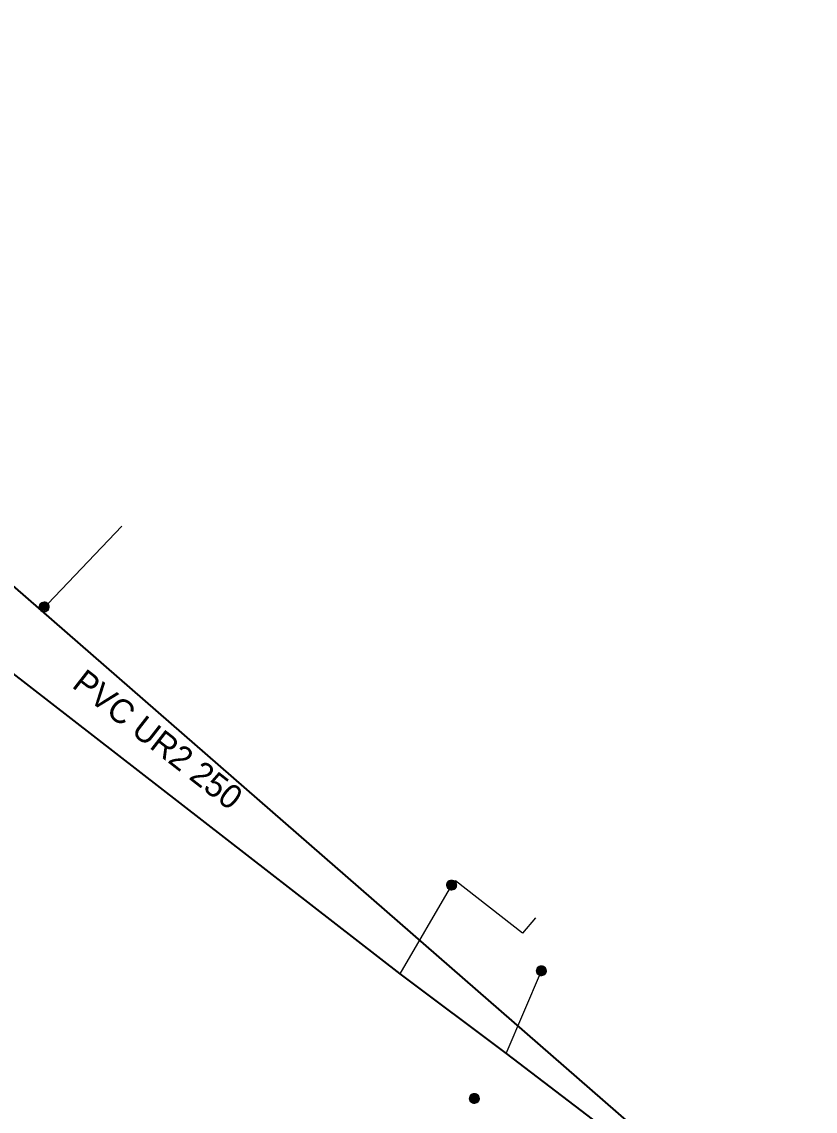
# Model space of a CAD drawing. Extents: x -873619 to -867639, y -1015082 to -1012326.
# Drawn here: x -868129.55 to -868093.3, y -1012775.89 to -1012726.16 of the extents above; entities that cross this region are included whole.
import ezdxf

# ---------------------------------------------------------------- set-up
doc = ezdxf.new("R2010")
doc.units = 0
doc.header["$LTSCALE"] = 0.44
for name, color, linetype, lineweight in [('1', 7, 'Continuous', 13), ('12', 7, 'Continuous', 13), ('21', 7, 'Continuous', 35), ('23', 7, 'Continuous', 25), ('3', 7, 'Continuous', 25), ('32', 7, 'Continuous', 13)]:
    doc.layers.add(name, color=color, linetype=linetype, lineweight=lineweight)

msp = doc.modelspace()

# ---------------------------------------------------------------- linework, layer by layer
at = {"layer": '1', "lineweight": 35}
msp.add_lwpolyline([(-868094.808, -1012782.506), (-868128.65, -1012753.034), (-868142.107, -1012741.315), (-868163.447, -1012723.713), (-868165.629, -1012721.604), (-868186.647, -1012703.368), (-868189.69, -1012700.802), (-868224.291, -1012669.746), (-868245.779, -1012651.034), (-868246.236, -1012651.387)], dxfattribs=at)
at = {"layer": '12'}
for points in [[(-868128.293, -1012752.869), (-868128.299, -1012752.817), (-868128.316, -1012752.767), (-868128.345, -1012752.723), (-868128.382, -1012752.686), (-868128.427, -1012752.659), (-868128.477, -1012752.642), (-868128.53, -1012752.638), (-868128.581, -1012752.645), (-868128.63, -1012752.664), (-868128.674, -1012752.693), (-868128.71, -1012752.732), (-868128.736, -1012752.777), (-868128.752, -1012752.828), (-868128.755, -1012752.88), (-868128.747, -1012752.932), (-868128.727, -1012752.981), (-868128.696, -1012753.024), (-868128.657, -1012753.058), (-868128.611, -1012753.084), (-868128.559, -1012753.098), (-868128.507, -1012753.1), (-868128.456, -1012753.09), (-868128.407, -1012753.069), (-868128.365, -1012753.038), (-868128.331, -1012752.997), (-868128.307, -1012752.951), (-868128.294, -1012752.9)], [(-868128.323, -1012752.869), (-868128.329, -1012752.82), (-868128.346, -1012752.774), (-868128.374, -1012752.734), (-868128.411, -1012752.702), (-868128.455, -1012752.68), (-868128.503, -1012752.669), (-868128.552, -1012752.669), (-868128.598, -1012752.682), (-868128.642, -1012752.706), (-868128.678, -1012752.739), (-868128.705, -1012752.78), (-868128.721, -1012752.827), (-868128.725, -1012752.876), (-868128.718, -1012752.924), (-868128.699, -1012752.969), (-868128.669, -1012753.009), (-868128.63, -1012753.04), (-868128.587, -1012753.06), (-868128.539, -1012753.07), (-868128.49, -1012753.068), (-868128.443, -1012753.053), (-868128.4, -1012753.028), (-868128.365, -1012752.994), (-868128.34, -1012752.952), (-868128.326, -1012752.905)], [(-868128.353, -1012752.869), (-868128.358, -1012752.824), (-868128.375, -1012752.782), (-868128.404, -1012752.747), (-868128.44, -1012752.72), (-868128.482, -1012752.703), (-868128.527, -1012752.698), (-868128.571, -1012752.704), (-868128.613, -1012752.723), (-868128.647, -1012752.751), (-868128.674, -1012752.788), (-868128.691, -1012752.83), (-868128.695, -1012752.875), (-868128.688, -1012752.92), (-868128.669, -1012752.961), (-868128.64, -1012752.995), (-868128.603, -1012753.021), (-868128.559, -1012753.037), (-868128.515, -1012753.04), (-868128.47, -1012753.032), (-868128.429, -1012753.012), (-868128.396, -1012752.983), (-868128.37, -1012752.945), (-868128.356, -1012752.902)], [(-868128.383, -1012752.869), (-868128.387, -1012752.828), (-868128.406, -1012752.791), (-868128.433, -1012752.76), (-868128.468, -1012752.739), (-868128.508, -1012752.728), (-868128.549, -1012752.73), (-868128.588, -1012752.743), (-868128.622, -1012752.767), (-868128.647, -1012752.799), (-868128.662, -1012752.837), (-868128.664, -1012752.878), (-868128.657, -1012752.918), (-868128.637, -1012752.954), (-868128.608, -1012752.983), (-868128.571, -1012753.002), (-868128.531, -1012753.01), (-868128.49, -1012753.006), (-868128.451, -1012752.991), (-868128.419, -1012752.965), (-868128.397, -1012752.931), (-868128.384, -1012752.892)], [(-868128.413, -1012752.869), (-868128.418, -1012752.833), (-868128.436, -1012752.801), (-868128.462, -1012752.776), (-868128.495, -1012752.761), (-868128.532, -1012752.758), (-868128.566, -1012752.766), (-868128.598, -1012752.786), (-868128.62, -1012752.814), (-868128.634, -1012752.848), (-868128.634, -1012752.885), (-868128.623, -1012752.92), (-868128.602, -1012752.949), (-868128.571, -1012752.97), (-868128.537, -1012752.98), (-868128.5, -1012752.978), (-868128.466, -1012752.964), (-868128.439, -1012752.941), (-868128.419, -1012752.909), (-868128.413, -1012752.874)], [(-868128.443, -1012752.869), (-868128.448, -1012752.838), (-868128.465, -1012752.812), (-868128.49, -1012752.795), (-868128.521, -1012752.788), (-868128.552, -1012752.792), (-868128.579, -1012752.809), (-868128.597, -1012752.833), (-868128.605, -1012752.864), (-868128.601, -1012752.894), (-868128.586, -1012752.922), (-868128.561, -1012752.941), (-868128.532, -1012752.95), (-868128.5, -1012752.947), (-868128.473, -1012752.933), (-868128.453, -1012752.909), (-868128.443, -1012752.88)], [(-868128.473, -1012752.869), (-868128.478, -1012752.845), (-868128.495, -1012752.827), (-868128.517, -1012752.818), (-868128.542, -1012752.821), (-868128.563, -1012752.835), (-868128.574, -1012752.857), (-868128.574, -1012752.882), (-868128.561, -1012752.903), (-868128.542, -1012752.917), (-868128.517, -1012752.92), (-868128.494, -1012752.911), (-868128.478, -1012752.893)], [(-868128.503, -1012752.869), (-868128.508, -1012752.854), (-868128.522, -1012752.848), (-868128.538, -1012752.852), (-868128.544, -1012752.866), (-868128.541, -1012752.881), (-868128.527, -1012752.89), (-868128.512, -1012752.887), (-868128.503, -1012752.875)]]:
    msp.add_lwpolyline(points, close=True, dxfattribs=at)
at = {"layer": '21'}
msp.add_lwpolyline([(-868134.19, -1012752.63), (-868112.27, -1012769.62), (-868107.42, -1012773.25), (-868101.75, -1012777.58), (-868093.15, -1012793.25), (-868087.37, -1012839.18), (-868062.459, -1012846.83), (-868020.28, -1012856.9)], dxfattribs=at)
at = {"layer": '23'}
msp.add_line((-868107.42, -1012773.25), (-868105.81, -1012769.48), dxfattribs=at)
msp.add_lwpolyline([(-868106.08, -1012767.07), (-868106.67, -1012767.76), (-868109.73, -1012765.38), (-868109.91, -1012765.57), (-868112.27, -1012769.62)], dxfattribs=at)
at = {"layer": '3'}
msp.add_line((-868128.666, -1012753.048), (-868124.972, -1012749.183), dxfattribs=at)
at = {"layer": '32'}
for points in [[(-868109.679, -1012765.569), (-868109.686, -1012765.517), (-868109.703, -1012765.467), (-868109.732, -1012765.423), (-868109.769, -1012765.386), (-868109.814, -1012765.359), (-868109.864, -1012765.342), (-868109.917, -1012765.338), (-868109.968, -1012765.345), (-868110.017, -1012765.364), (-868110.061, -1012765.393), (-868110.097, -1012765.432), (-868110.123, -1012765.477), (-868110.139, -1012765.528), (-868110.142, -1012765.58), (-868110.134, -1012765.632), (-868110.114, -1012765.681), (-868110.083, -1012765.724), (-868110.044, -1012765.758), (-868109.998, -1012765.784), (-868109.946, -1012765.798), (-868109.894, -1012765.8), (-868109.843, -1012765.79), (-868109.794, -1012765.769), (-868109.752, -1012765.738), (-868109.718, -1012765.697), (-868109.694, -1012765.651), (-868109.681, -1012765.6)], [(-868109.71, -1012765.569), (-868109.716, -1012765.52), (-868109.733, -1012765.474), (-868109.761, -1012765.434), (-868109.798, -1012765.402), (-868109.842, -1012765.38), (-868109.89, -1012765.369), (-868109.939, -1012765.369), (-868109.985, -1012765.382), (-868110.029, -1012765.406), (-868110.065, -1012765.439), (-868110.092, -1012765.48), (-868110.108, -1012765.527), (-868110.112, -1012765.576), (-868110.105, -1012765.624), (-868110.086, -1012765.669), (-868110.056, -1012765.709), (-868110.017, -1012765.74), (-868109.973, -1012765.76), (-868109.926, -1012765.77), (-868109.877, -1012765.768), (-868109.83, -1012765.753), (-868109.787, -1012765.728), (-868109.752, -1012765.694), (-868109.727, -1012765.652), (-868109.713, -1012765.605)], [(-868109.74, -1012765.569), (-868109.745, -1012765.524), (-868109.762, -1012765.482), (-868109.791, -1012765.447), (-868109.826, -1012765.42), (-868109.869, -1012765.403), (-868109.914, -1012765.398), (-868109.958, -1012765.404), (-868110, -1012765.423), (-868110.034, -1012765.451), (-868110.061, -1012765.488), (-868110.078, -1012765.53), (-868110.081, -1012765.575), (-868110.075, -1012765.62), (-868110.056, -1012765.661), (-868110.027, -1012765.695), (-868109.99, -1012765.721), (-868109.946, -1012765.737), (-868109.902, -1012765.74), (-868109.857, -1012765.732), (-868109.816, -1012765.712), (-868109.782, -1012765.683), (-868109.757, -1012765.645), (-868109.743, -1012765.602)], [(-868109.77, -1012765.569), (-868109.774, -1012765.528), (-868109.793, -1012765.491), (-868109.82, -1012765.46), (-868109.855, -1012765.439), (-868109.895, -1012765.428), (-868109.936, -1012765.43), (-868109.975, -1012765.443), (-868110.009, -1012765.467), (-868110.034, -1012765.499), (-868110.049, -1012765.537), (-868110.051, -1012765.578), (-868110.044, -1012765.618), (-868110.024, -1012765.654), (-868109.995, -1012765.683), (-868109.958, -1012765.702), (-868109.918, -1012765.71), (-868109.877, -1012765.706), (-868109.838, -1012765.691), (-868109.806, -1012765.665), (-868109.784, -1012765.631), (-868109.771, -1012765.592)], [(-868109.799, -1012765.569), (-868109.804, -1012765.533), (-868109.823, -1012765.501), (-868109.848, -1012765.476), (-868109.882, -1012765.461), (-868109.919, -1012765.458), (-868109.953, -1012765.466), (-868109.985, -1012765.486), (-868110.007, -1012765.514), (-868110.021, -1012765.548), (-868110.021, -1012765.585), (-868110.01, -1012765.62), (-868109.989, -1012765.649), (-868109.958, -1012765.67), (-868109.924, -1012765.68), (-868109.887, -1012765.678), (-868109.853, -1012765.664), (-868109.826, -1012765.641), (-868109.806, -1012765.609), (-868109.799, -1012765.574)], [(-868109.83, -1012765.569), (-868109.835, -1012765.538), (-868109.852, -1012765.512), (-868109.877, -1012765.495), (-868109.907, -1012765.488), (-868109.939, -1012765.492), (-868109.966, -1012765.509), (-868109.983, -1012765.533), (-868109.992, -1012765.564), (-868109.988, -1012765.594), (-868109.973, -1012765.622), (-868109.948, -1012765.641), (-868109.919, -1012765.65), (-868109.887, -1012765.647), (-868109.86, -1012765.633), (-868109.84, -1012765.609), (-868109.83, -1012765.58)], [(-868109.86, -1012765.569), (-868109.865, -1012765.545), (-868109.882, -1012765.527), (-868109.904, -1012765.518), (-868109.929, -1012765.521), (-868109.95, -1012765.535), (-868109.961, -1012765.557), (-868109.961, -1012765.582), (-868109.948, -1012765.603), (-868109.929, -1012765.617), (-868109.904, -1012765.62), (-868109.88, -1012765.611), (-868109.865, -1012765.593)], [(-868109.89, -1012765.569), (-868109.895, -1012765.554), (-868109.909, -1012765.548), (-868109.924, -1012765.552), (-868109.931, -1012765.566), (-868109.928, -1012765.581), (-868109.914, -1012765.59), (-868109.899, -1012765.587), (-868109.89, -1012765.575)], [(-868105.58, -1012769.479), (-868105.586, -1012769.427), (-868105.603, -1012769.377), (-868105.632, -1012769.333), (-868105.669, -1012769.296), (-868105.714, -1012769.269), (-868105.764, -1012769.252), (-868105.817, -1012769.248), (-868105.869, -1012769.255), (-868105.918, -1012769.274), (-868105.961, -1012769.303), (-868105.997, -1012769.342), (-868106.023, -1012769.387), (-868106.039, -1012769.438), (-868106.042, -1012769.49), (-868106.034, -1012769.542), (-868106.014, -1012769.591), (-868105.983, -1012769.634), (-868105.944, -1012769.668), (-868105.898, -1012769.694), (-868105.847, -1012769.708), (-868105.794, -1012769.71), (-868105.743, -1012769.7), (-868105.695, -1012769.679), (-868105.652, -1012769.648), (-868105.618, -1012769.607), (-868105.594, -1012769.561), (-868105.581, -1012769.51)], [(-868105.61, -1012769.479), (-868105.616, -1012769.43), (-868105.633, -1012769.384), (-868105.661, -1012769.344), (-868105.698, -1012769.312), (-868105.742, -1012769.29), (-868105.79, -1012769.279), (-868105.839, -1012769.279), (-868105.886, -1012769.292), (-868105.929, -1012769.316), (-868105.965, -1012769.349), (-868105.992, -1012769.39), (-868106.008, -1012769.437), (-868106.012, -1012769.486), (-868106.005, -1012769.534), (-868105.986, -1012769.579), (-868105.956, -1012769.619), (-868105.918, -1012769.65), (-868105.874, -1012769.67), (-868105.826, -1012769.68), (-868105.777, -1012769.678), (-868105.73, -1012769.663), (-868105.687, -1012769.638), (-868105.652, -1012769.604), (-868105.627, -1012769.562), (-868105.613, -1012769.515)], [(-868105.64, -1012769.479), (-868105.646, -1012769.434), (-868105.663, -1012769.392), (-868105.691, -1012769.357), (-868105.727, -1012769.33), (-868105.769, -1012769.313), (-868105.814, -1012769.308), (-868105.858, -1012769.314), (-868105.9, -1012769.333), (-868105.934, -1012769.361), (-868105.962, -1012769.398), (-868105.978, -1012769.44), (-868105.982, -1012769.485), (-868105.975, -1012769.53), (-868105.956, -1012769.571), (-868105.927, -1012769.605), (-868105.89, -1012769.631), (-868105.847, -1012769.647), (-868105.802, -1012769.65), (-868105.757, -1012769.642), (-868105.717, -1012769.622), (-868105.683, -1012769.593), (-868105.657, -1012769.555), (-868105.643, -1012769.512)], [(-868105.67, -1012769.479), (-868105.674, -1012769.438), (-868105.693, -1012769.401), (-868105.72, -1012769.37), (-868105.755, -1012769.349), (-868105.795, -1012769.338), (-868105.836, -1012769.34), (-868105.875, -1012769.353), (-868105.909, -1012769.377), (-868105.934, -1012769.409), (-868105.949, -1012769.447), (-868105.951, -1012769.488), (-868105.944, -1012769.528), (-868105.924, -1012769.564), (-868105.895, -1012769.593), (-868105.858, -1012769.612), (-868105.818, -1012769.62), (-868105.777, -1012769.616), (-868105.739, -1012769.601), (-868105.706, -1012769.575), (-868105.684, -1012769.541), (-868105.671, -1012769.502)], [(-868105.7, -1012769.479), (-868105.705, -1012769.443), (-868105.723, -1012769.411), (-868105.749, -1012769.386), (-868105.782, -1012769.371), (-868105.819, -1012769.368), (-868105.853, -1012769.376), (-868105.885, -1012769.396), (-868105.907, -1012769.424), (-868105.921, -1012769.458), (-868105.921, -1012769.495), (-868105.91, -1012769.53), (-868105.889, -1012769.559), (-868105.858, -1012769.58), (-868105.824, -1012769.59), (-868105.787, -1012769.588), (-868105.753, -1012769.574), (-868105.726, -1012769.551), (-868105.706, -1012769.519), (-868105.7, -1012769.484)], [(-868105.73, -1012769.479), (-868105.735, -1012769.448), (-868105.752, -1012769.422), (-868105.777, -1012769.405), (-868105.808, -1012769.398), (-868105.839, -1012769.402), (-868105.866, -1012769.419), (-868105.884, -1012769.443), (-868105.892, -1012769.474), (-868105.888, -1012769.504), (-868105.873, -1012769.532), (-868105.848, -1012769.551), (-868105.819, -1012769.56), (-868105.788, -1012769.557), (-868105.76, -1012769.543), (-868105.74, -1012769.519), (-868105.73, -1012769.49)], [(-868105.76, -1012769.479), (-868105.765, -1012769.455), (-868105.782, -1012769.437), (-868105.804, -1012769.428), (-868105.829, -1012769.431), (-868105.85, -1012769.445), (-868105.861, -1012769.467), (-868105.861, -1012769.492), (-868105.848, -1012769.513), (-868105.829, -1012769.527), (-868105.804, -1012769.53), (-868105.781, -1012769.521), (-868105.765, -1012769.503)], [(-868105.79, -1012769.479), (-868105.795, -1012769.464), (-868105.809, -1012769.458), (-868105.825, -1012769.462), (-868105.831, -1012769.476), (-868105.828, -1012769.491), (-868105.815, -1012769.5), (-868105.799, -1012769.497), (-868105.79, -1012769.485)], [(-868108.64, -1012775.309), (-868108.646, -1012775.257), (-868108.663, -1012775.207), (-868108.692, -1012775.163), (-868108.729, -1012775.126), (-868108.774, -1012775.099), (-868108.824, -1012775.082), (-868108.877, -1012775.078), (-868108.929, -1012775.085), (-868108.978, -1012775.104), (-868109.021, -1012775.133), (-868109.057, -1012775.172), (-868109.083, -1012775.217), (-868109.099, -1012775.268), (-868109.102, -1012775.32), (-868109.094, -1012775.372), (-868109.074, -1012775.421), (-868109.043, -1012775.464), (-868109.004, -1012775.498), (-868108.958, -1012775.524), (-868108.907, -1012775.538), (-868108.854, -1012775.54), (-868108.803, -1012775.53), (-868108.755, -1012775.509), (-868108.712, -1012775.478), (-868108.678, -1012775.437), (-868108.654, -1012775.391), (-868108.642, -1012775.34)], [(-868108.67, -1012775.309), (-868108.676, -1012775.26), (-868108.693, -1012775.214), (-868108.721, -1012775.174), (-868108.758, -1012775.142), (-868108.802, -1012775.12), (-868108.85, -1012775.109), (-868108.899, -1012775.109), (-868108.946, -1012775.122), (-868108.989, -1012775.146), (-868109.025, -1012775.179), (-868109.052, -1012775.22), (-868109.068, -1012775.267), (-868109.072, -1012775.316), (-868109.065, -1012775.364), (-868109.046, -1012775.409), (-868109.016, -1012775.449), (-868108.978, -1012775.48), (-868108.934, -1012775.5), (-868108.886, -1012775.51), (-868108.837, -1012775.508), (-868108.79, -1012775.493), (-868108.747, -1012775.468), (-868108.713, -1012775.434), (-868108.687, -1012775.392), (-868108.673, -1012775.345)], [(-868108.7, -1012775.309), (-868108.706, -1012775.264), (-868108.723, -1012775.222), (-868108.751, -1012775.187), (-868108.787, -1012775.16), (-868108.829, -1012775.143), (-868108.874, -1012775.138), (-868108.919, -1012775.144), (-868108.96, -1012775.163), (-868108.995, -1012775.191), (-868109.022, -1012775.228), (-868109.038, -1012775.27), (-868109.042, -1012775.315), (-868109.035, -1012775.36), (-868109.016, -1012775.401), (-868108.987, -1012775.435), (-868108.95, -1012775.461), (-868108.907, -1012775.477), (-868108.862, -1012775.48), (-868108.817, -1012775.472), (-868108.777, -1012775.452), (-868108.743, -1012775.423), (-868108.717, -1012775.385), (-868108.703, -1012775.342)], [(-868108.73, -1012775.309), (-868108.735, -1012775.268), (-868108.753, -1012775.231), (-868108.78, -1012775.2), (-868108.815, -1012775.179), (-868108.855, -1012775.168), (-868108.896, -1012775.17), (-868108.935, -1012775.183), (-868108.969, -1012775.207), (-868108.994, -1012775.239), (-868109.009, -1012775.277), (-868109.012, -1012775.318), (-868109.004, -1012775.358), (-868108.984, -1012775.394), (-868108.955, -1012775.423), (-868108.918, -1012775.442), (-868108.878, -1012775.45), (-868108.837, -1012775.446), (-868108.799, -1012775.431), (-868108.767, -1012775.405), (-868108.744, -1012775.371), (-868108.731, -1012775.332)], [(-868108.76, -1012775.309), (-868108.765, -1012775.273), (-868108.783, -1012775.241), (-868108.809, -1012775.216), (-868108.843, -1012775.201), (-868108.879, -1012775.198), (-868108.914, -1012775.206), (-868108.945, -1012775.226), (-868108.968, -1012775.254), (-868108.981, -1012775.288), (-868108.981, -1012775.325), (-868108.97, -1012775.36), (-868108.949, -1012775.389), (-868108.919, -1012775.41), (-868108.884, -1012775.42), (-868108.847, -1012775.418), (-868108.813, -1012775.404), (-868108.786, -1012775.381), (-868108.767, -1012775.349), (-868108.76, -1012775.314)], [(-868108.79, -1012775.309), (-868108.795, -1012775.278), (-868108.812, -1012775.252), (-868108.838, -1012775.235), (-868108.868, -1012775.228), (-868108.899, -1012775.232), (-868108.926, -1012775.249), (-868108.944, -1012775.273), (-868108.952, -1012775.304), (-868108.948, -1012775.334), (-868108.933, -1012775.362), (-868108.909, -1012775.381), (-868108.879, -1012775.39), (-868108.848, -1012775.387), (-868108.82, -1012775.373), (-868108.8, -1012775.349), (-868108.79, -1012775.32)], [(-868108.82, -1012775.309), (-868108.825, -1012775.285), (-868108.842, -1012775.267), (-868108.865, -1012775.258), (-868108.889, -1012775.261), (-868108.91, -1012775.275), (-868108.921, -1012775.297), (-868108.921, -1012775.322), (-868108.909, -1012775.343), (-868108.889, -1012775.357), (-868108.864, -1012775.36), (-868108.841, -1012775.351), (-868108.825, -1012775.333)], [(-868108.85, -1012775.309), (-868108.855, -1012775.294), (-868108.87, -1012775.288), (-868108.885, -1012775.292), (-868108.892, -1012775.306), (-868108.888, -1012775.321), (-868108.875, -1012775.33), (-868108.86, -1012775.327), (-868108.85, -1012775.315)]]:
    msp.add_lwpolyline(points, close=True, dxfattribs=at)

# ---------------------------------------------------------------- texts
at = {"layer": '1'}
msp.add_text('PVC UR2 250 ', height=1.1, rotation=322, dxfattribs=at).set_placement((-868127.306, -1012756.509))

doc.saveas('drawing.dxf')
